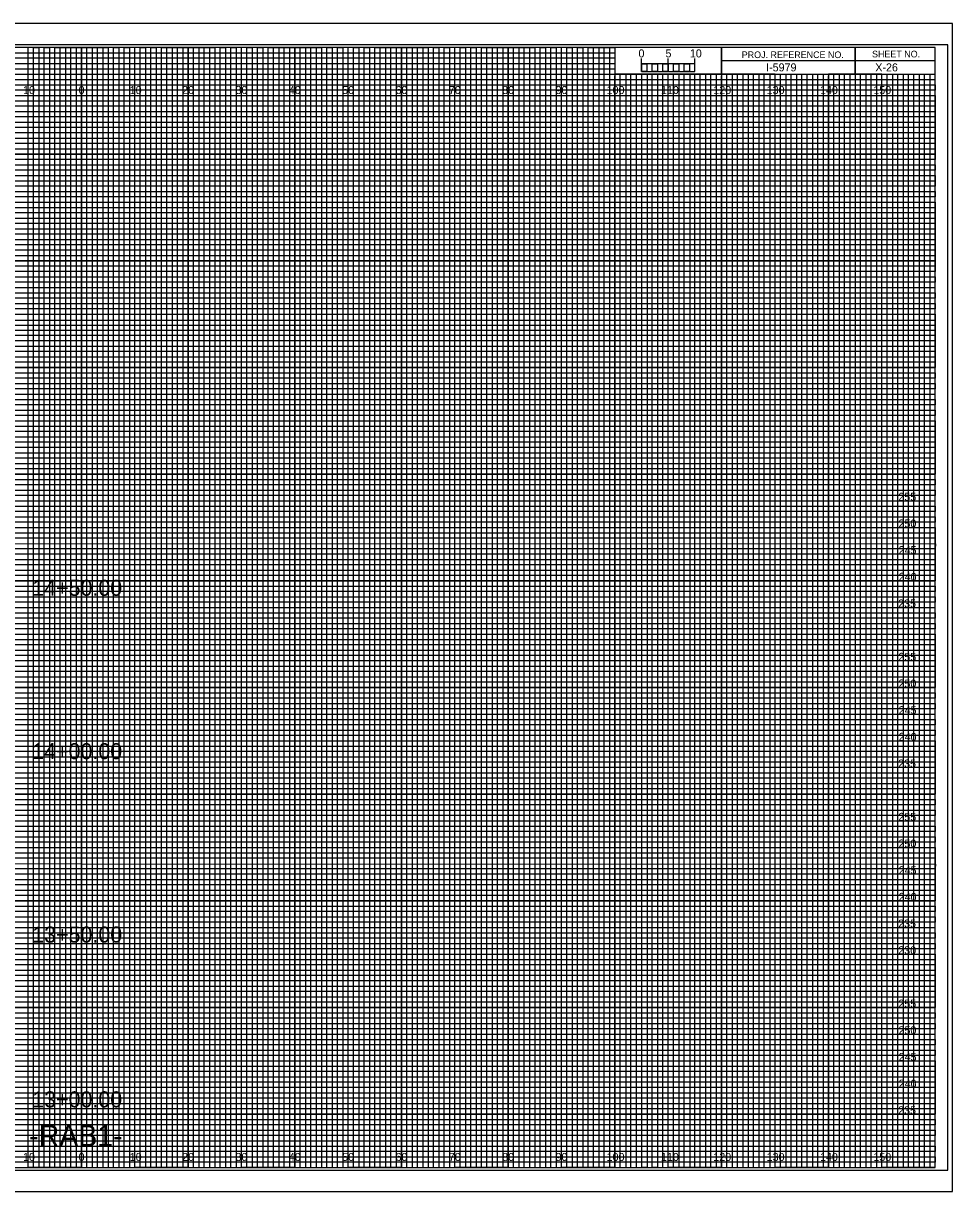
# Model space of a CAD drawing. Extents: x -13 to 323, y -5 to 434.
# Drawn here: x 149.1 to 323.3, y 215.5 to 434.5 of the extents above; entities that cross this region are included whole.
import ezdxf

# ---------------------------------------------------------------- set-up
doc = ezdxf.new("R2010")
doc.units = 0
for name, color, linetype in [('Exist CMT Pavement', 7, 'Continuous'), ('Exist Cross Section Cell', 7, 'Continuous'), ('Exist XS Center Line Elevation Label', 7, 'Continuous'), ('Exist XS Ground Line', 7, 'Continuous'), ('Prop CMT Conc Surface', 7, 'Continuous'), ('Prop CMT Concrete Structures', 7, 'Continuous'), ('Prop CMT DNC', 7, 'Continuous'), ('Prop CMT Pvmt Course 1 CG', 7, 'Continuous'), ('Prop CMT Pvmt Course 1 Wedge', 7, 'Continuous'), ('Prop CMT Pvmt Course 2', 7, 'Continuous'), ('Prop CMT Pvmt Course 2 Wedge', 7, 'Continuous'), ('Prop CMT Pvmt Course 3', 7, 'Continuous'), ('Prop CMT Pvmt Surface', 7, 'Continuous'), ('Prop CMT Pvmt Wedge Surface 1', 7, 'Continuous'), ('Prop CMT Shear Line', 7, 'Continuous'), ('Prop CMT Slope Grass', 7, 'Continuous'), ('Prop CMT Subgrade Earthwork', 7, 'Continuous')]:
    doc.layers.add(name, color=color, linetype=linetype)

msp = doc.modelspace()

# ---------------------------------------------------------------- linework, layer by layer
at = {"layer": 'Exist XS Center Line Elevation Label'}
for points in [[(145, 220), (155, 220), (155, 430), (165, 430), (165, 220), (175, 220), (175, 430), (185, 430), (185, 220), (195, 220), (195, 430), (205, 430), (205, 220), (215, 220), (215, 430), (225, 430), (225, 220), (235, 220), (235, 430), (245, 430), (245, 220), (255, 220), (255, 430), (259.93, 430), (260, 430), (260, 425), (264.99, 425), (264.99, 220), (275, 220), (275, 425), (285, 425), (285, 220), (295, 220), (295, 425), (305, 425), (305, 220), (315, 220), (315, 425)], [(0, 425), (275, 425)], [(0, 405), (320, 405), (320, 415), (0, 415)], [(0, 385), (320, 385), (320, 395), (0, 395)], [(0, 365), (320, 365), (320, 375), (0, 375)], [(0, 345), (320, 345), (320, 355), (0, 355)], [(0, 325), (320, 325), (320, 335), (0, 335)], [(0, 305), (320, 305), (320, 315), (0, 315)], [(0, 285), (320, 285), (320, 295), (0, 295)], [(0, 265), (320, 265), (320, 275), (0, 275)], [(0, 245), (320, 245), (320, 255), (0, 255)], [(0, 225), (320, 225), (320, 235), (0, 235)]]:
    msp.add_lwpolyline(points, dxfattribs=at)
at = {"layer": 'Exist XS Ground Line'}
for p, q in [((150, 430), (140, 430)), ((150, 220), (150, 430)), ((170, 430), (160, 430)), ((160, 430), (160, 220)), ((170, 220), (170, 430)), ((190, 430), (180, 430)), ((180, 430), (180, 220)), ((190, 220), (190, 430)), ((210, 430), (200, 430)), ((200, 430), (200, 220)), ((210, 220), (210, 430)), ((230, 430), (220, 430)), ((220, 430), (220, 220)), ((230, 220), (230, 430)), ((250, 430), (240, 430)), ((240, 430), (240, 220)), ((250, 220), (250, 430)), ((260, 430), (260, 220)), ((270, 220), (270, 425)), ((290, 425), (280, 425)), ((280, 425), (280, 220)), ((290, 220), (290, 425)), ((310, 425), (300, 425)), ((300, 425), (300, 220)), ((310, 220), (310, 425)), ((160, 220), (150, 220)), ((180, 220), (170, 220)), ((200, 220), (190, 220)), ((220, 220), (210, 220)), ((240, 220), (230, 220)), ((260, 220), (250, 220)), ((280, 220), (270, 220)), ((300, 220), (290, 220)), ((320, 220), (310, 220)), ((320, 220), (320, 220))]:
    msp.add_line(p, q, dxfattribs=at)
for points in [[(0, 420), (320, 420), (320, 410), (0, 410)], [(0, 400), (320, 400), (320, 390), (0, 390)], [(0, 380), (320, 380), (320, 370), (0, 370)], [(0, 360), (320, 360), (320, 350), (0, 350)], [(0, 340), (320, 340), (320, 330), (0, 330)], [(0, 320), (320, 320), (320, 310), (0, 310)], [(0, 300), (320, 300), (320, 290), (0, 290)], [(0, 280), (320, 280), (320, 270), (0, 270)], [(0, 260), (320, 260), (320, 250), (0, 250)], [(0, 240), (320, 240), (320, 230), (0, 230)]]:
    msp.add_lwpolyline(points, dxfattribs=at)
at = {"layer": 'Prop CMT Conc Surface'}
msp.add_lwpolyline([(-13.4, 215.5), (323.3, 215.5), (323.3, 434.5), (-13.4, 434.5)], close=True, dxfattribs=at)
at = {"layer": 'Prop CMT Concrete Structures'}
for p, q in [((305, 430), (305, 425)), ((305, 425), (305, 430)), ((280, 427.5), (280, 425)), ((320, 427.49), (280, 427.49)), ((280, 425), (320, 425))]:
    msp.add_line(p, q, dxfattribs=at)
for points in [[(320, 430), (0, 430), (0, 220), (320, 220)], [(280, 430), (260, 430), (260, 425.03), (280, 425.03)], [(320, 430), (280, 430), (280, 425), (320, 425)]]:
    msp.add_lwpolyline(points, close=True, dxfattribs=at)
at = {"layer": 'Prop CMT DNC'}
for p, q in [((267, 425), (266.01, 425)), ((266.01, 425), (266.01, 220)), ((267, 220), (267, 425)), ((269, 425), (268, 425)), ((268, 425), (268, 220)), ((269, 220), (269, 425)), ((266.01, 220), (265, 220)), ((268, 220), (267, 220))]:
    msp.add_line(p, q, dxfattribs=at)
for points in [[(150, 220), (151, 220), (151, 430), (152, 430), (152, 220)], [(152, 220), (153, 220), (153, 430), (154, 430), (154, 220)], [(155, 220), (156, 220), (156, 430), (157, 430), (157, 220)], [(157, 220), (158, 220), (158, 430), (159, 430), (159, 220)], [(160, 220), (161, 220), (161, 430), (162, 430), (162, 220)], [(162, 220), (163, 220), (163, 430), (164, 430), (164, 220)], [(165, 220), (166, 220), (166, 430), (167, 430), (167, 220)], [(167, 220), (168, 220), (168, 430), (169, 430), (169, 220)], [(170, 220), (171, 220), (171, 430), (172, 430), (172, 220)], [(172, 220), (173, 220), (173, 430), (174, 430), (174, 220)], [(175, 220), (176, 220), (176, 430), (177, 430), (177, 220)], [(177, 220), (178, 220), (178, 430), (179, 430), (179, 220)], [(180, 220), (181, 220), (181, 430), (182, 430), (182, 220)], [(182, 220), (183, 220), (183, 430), (184, 430), (184, 220)], [(185, 220), (186, 220), (186, 430), (187, 430), (187, 220)], [(187, 220), (188, 220), (188, 430), (189, 430), (189, 220)], [(190, 220), (191, 220), (191, 430), (192, 430), (192, 220)], [(192, 220), (193, 220), (193, 430), (194, 430), (194, 220)], [(195, 220), (196, 220), (196, 430), (197, 430), (197, 220)], [(197, 220), (198, 220), (198, 430), (199, 430), (199, 220)], [(200, 220), (201, 220), (201, 430), (202, 430), (202, 220)], [(202, 220), (203, 220), (203, 430), (204, 430), (204, 220)], [(205, 220), (206, 220), (206, 430), (207, 430), (207, 220)], [(207, 220), (208, 220), (208, 430), (209, 430), (209, 220)], [(210, 220), (211, 220), (211, 430), (212, 430), (212, 220)], [(212, 220), (213, 220), (213, 430), (214, 430), (214, 220)], [(215, 220), (216, 220), (216, 430), (217, 430), (217, 220)], [(217, 220), (218, 220), (218, 430), (219, 430), (219, 220)], [(220, 220), (221, 220), (221, 430), (222, 430), (222, 220)], [(222, 220), (223, 220), (223, 430), (224, 430), (224, 220)], [(225, 220), (226, 220), (226, 430), (227, 430), (227, 220)], [(227, 220), (228, 220), (228, 430), (229, 430), (229, 220)], [(230, 220), (231, 220), (231, 430), (232, 430), (232, 220)], [(232, 220), (233, 220), (233, 430), (234, 430), (234, 220)], [(235, 220), (236, 220), (236, 430), (237, 430), (237, 220)], [(237, 220), (238, 220), (238, 430), (239, 430), (239, 220)], [(240, 220), (241, 220), (241, 430), (242, 430), (242, 220)], [(242, 220), (243, 220), (243, 430), (244, 430), (244, 220)], [(245, 220), (246, 220), (246, 430), (247, 430), (247, 220)], [(247, 220), (248, 220), (248, 430), (249, 430), (249, 220)], [(250, 220), (251, 220), (251, 430), (252, 430), (252, 220)], [(252, 220), (253, 220), (253, 430), (254, 430), (254, 220)], [(255, 220), (256, 220), (256, 430), (257, 430), (257, 220)], [(257, 220), (258, 220), (258, 430), (259, 430), (259, 220)], [(260, 220), (261, 220), (261, 425), (262.02, 425), (262.02, 220)], [(262, 220), (263, 220), (263, 425), (263.99, 425), (263.99, 220)], [(270, 220), (270.98, 220), (270.98, 425), (272, 425), (272, 220)], [(272, 220), (273, 220), (273, 425), (274.05, 425), (274.05, 220)], [(275, 220), (276, 220), (276, 425), (277, 425), (277, 220)], [(277, 220), (278, 220), (278, 425), (279, 425), (279, 220)], [(280, 220), (281, 220), (281, 425), (282, 425), (282, 220)], [(282, 220), (283, 220), (283, 425), (284, 425), (284, 220)], [(285, 220), (286, 220), (286, 425), (287, 425), (287, 220)], [(287, 220), (288, 220), (288, 425), (289, 425), (289, 220)], [(290, 220), (291, 220), (291, 425), (292, 425), (292, 220)], [(292, 220), (293, 220), (293, 425), (294, 425), (294, 220)], [(295, 220), (296, 220), (296, 425), (297, 425), (297, 220)], [(297, 220), (298, 220), (298, 425), (299, 425), (299, 220)], [(300, 220), (301, 220), (301, 425), (302, 425), (302, 220)], [(302, 220), (303, 220), (303, 425), (304, 425), (304, 220)], [(305, 220), (306, 220), (306, 425), (307, 425), (307, 220)], [(307, 220), (308, 220), (308, 425), (309, 425), (309, 220)], [(310, 220), (311, 220), (311, 425), (312, 425), (312, 220)], [(312, 220), (313, 220), (313, 425), (314, 425), (314, 220)], [(315, 220), (316, 220), (316, 425), (317, 425), (317, 220)], [(317, 220), (318, 220), (318, 425), (319, 425), (319, 220)]]:
    msp.add_lwpolyline(points, dxfattribs=at)
at = {"layer": 'Prop CMT Pvmt Course 1 Wedge'}
for p, q in [((323.3, 434.5), (-13.4, 434.5)), ((-13.4, 215.5), (323.3, 215.5))]:
    msp.add_line(p, q, dxfattribs=at)
at = {"layer": 'Prop CMT Pvmt Course 2'}
msp.add_lwpolyline([(-10.8, 219.5), (322.4, 219.5), (322.4, 430.5), (-10.8, 430.5)], close=True, dxfattribs=at)
at = {"layer": 'Prop CMT Pvmt Course 3'}
for p, q in [((150, 220), (150, 430)), ((160, 220), (160, 430)), ((170, 220), (170, 430)), ((180, 220), (180, 430)), ((190, 220), (190, 430)), ((200, 220), (200, 430)), ((210, 220), (210, 430)), ((220, 220), (220, 430)), ((230, 220), (230, 430)), ((240, 220), (240, 430)), ((250, 220), (250, 430)), ((260, 220), (260, 424.69)), ((270, 220), (270, 424.69)), ((280, 220), (280, 424.69)), ((290, 220), (290, 424.69)), ((300, 220), (300, 424.69)), ((310, 220), (310, 424.69)), ((0, 420), (320, 420)), ((0, 410), (320, 410)), ((0, 400), (320, 400)), ((0, 390), (320, 390)), ((0, 380), (320, 380)), ((0, 370), (320, 370)), ((0, 360), (320, 360)), ((0, 350), (320, 350)), ((0, 340), (320, 340)), ((0, 330), (320, 330)), ((0, 320), (320, 320)), ((0, 310), (320, 310)), ((0, 300), (320, 300)), ((0, 290), (320, 290)), ((0, 280), (320, 280)), ((0, 270), (320, 270)), ((0, 260), (320, 260)), ((0, 250), (320, 250)), ((0, 240), (320, 240)), ((0, 230), (320, 230))]:
    msp.add_line(p, q, dxfattribs=at)
at = {"layer": 'Prop CMT Slope Grass'}
for p, q in [((265, 425.49), (265, 427.9)), ((265, 426.9), (265, 427.9)), ((270, 425.49), (270, 427.9)), ((275, 425.49), (275, 427.9)), ((275, 426.9), (275, 427.9))]:
    msp.add_line(p, q, dxfattribs=at)
for points in [[(275, 426.9), (265, 426.9), (265, 425.49), (275, 425.49)], [(265, 426.9), (266, 426.9), (266, 425.49), (265, 425.49)], [(267, 426.9), (268, 426.9), (268, 425.49), (267, 425.49)], [(269, 426.9), (270, 426.9), (270, 425.49), (269, 425.49)], [(271, 426.9), (272, 426.9), (272, 425.49), (271, 425.49)], [(273, 426.9), (274, 426.9), (274, 425.49), (273, 425.49)]]:
    msp.add_lwpolyline(points, close=True, dxfattribs=at)
at = {"layer": 'Prop CMT Subgrade Earthwork'}
for p, q in [((0, 429), (260, 429)), ((260, 427.98), (0, 427.98)), ((260, 429), (260, 427.98)), ((0, 427), (260, 427)), ((260, 425.89), (0, 425.89)), ((260, 427), (260, 425.89)), ((0, 424), (320, 424))]:
    msp.add_line(p, q, dxfattribs=at)
for points in [[(0, 423), (270, 423), (320, 423), (320, 422), (0, 422)], [(0, 421), (320, 421), (320, 419), (0, 419)], [(0, 418), (320, 418), (320, 417), (0, 416.98)], [(0, 416), (320, 416), (320, 414), (0, 414)], [(0, 413), (320, 413), (320, 412), (0, 412)], [(0, 411), (320, 411), (320, 409), (0, 409)], [(0, 408), (320, 408), (320, 407), (0, 407)], [(0, 406), (320, 406), (320, 404), (0, 404)], [(0, 403), (320, 403), (320, 402), (0, 402)], [(0, 401), (320, 401), (320, 399), (0, 399)], [(0, 398), (320, 398), (320, 397), (0, 397)], [(0, 396), (320, 396), (320, 393.95), (320, 393), (320, 392), (0, 392)], [(0, 394), (320, 394), (320, 393), (0, 393)], [(0, 391), (320, 391), (320, 389), (0, 389.03)], [(0, 389.03), (320, 389), (320, 388), (0, 388)], [(0, 387), (320, 387), (320, 386), (0, 386)], [(0, 384), (320, 384), (320, 383), (0, 383)], [(0, 382), (320, 382), (320, 381), (0, 381)], [(-0.07, 378.89), (320, 378.89), (320, 377.88), (-0.07, 377.88)], [(0, 377), (320, 377), (320, 376), (0, 376)], [(0, 374), (320, 374), (320, 373), (0, 373)], [(0, 372), (320, 372), (320, 371), (0, 371)], [(0, 369), (320, 369), (320, 368), (0, 368)], [(0, 367), (320, 367), (320, 366), (0, 366)], [(0, 364), (320, 364), (320, 363), (0, 363)], [(0, 362), (320, 362), (320, 361), (0, 361)], [(0, 359), (320, 359), (319.99, 357.98), (0, 358)], [(0, 357), (320, 357), (320, 356), (0, 356)], [(0, 354), (320, 354), (320, 353), (0, 353)], [(0, 352), (320, 352), (320, 351), (0, 351)], [(0, 349), (320, 349), (320, 348), (0, 348)], [(0, 347), (320, 347), (320, 346), (0, 346)], [(0, 344), (320, 344), (320, 343), (0, 343)], [(0, 342), (320, 342), (320, 341), (0, 341)], [(0, 339), (320, 339), (320, 338), (0, 338)], [(0, 336.99), (320.07, 336.91), (320, 336), (0, 336)], [(0, 334), (320, 334), (320, 333), (0, 333)], [(0, 332), (320, 332), (320, 331), (0, 331)], [(0, 329), (320, 329), (320, 328), (0, 328)], [(0, 327), (320, 327), (320, 326), (0, 326)], [(0, 324), (320, 324), (320, 323), (0, 323)], [(0, 322), (320, 322), (320, 321), (0, 321)], [(0, 319), (320, 319), (320, 318), (0, 318)], [(0, 317), (320, 317), (320, 316), (0, 316)], [(0, 314), (320, 314), (320, 313), (0, 313)], [(0, 312), (320, 312), (320, 311), (0, 311)], [(0, 309), (320, 309), (320, 308), (0, 308)], [(0, 307), (320, 307), (320, 306), (0, 306)], [(0, 304), (320, 304), (320, 303), (0, 303)], [(0, 302), (320, 302), (320, 301), (0, 301)], [(0, 299), (320, 299), (319.99, 297.98), (0, 298)], [(0, 297), (320, 297), (320, 296), (0, 296)], [(0, 294), (320, 294), (320, 293), (0, 293)], [(0, 292), (320, 292), (320, 291), (0, 291)], [(0, 289), (320, 289), (320, 288), (0, 288)], [(0, 287), (320, 287), (320, 286), (0, 286)], [(0, 284), (320, 284), (320, 283), (0, 283)], [(0, 282), (320, 282), (320, 281), (0, 281)], [(0, 279), (320, 279), (320, 278), (0, 278)], [(0, 276.99), (320.07, 276.91), (320, 276), (0, 276)], [(0, 274), (320, 274), (320, 273), (0, 273)], [(0, 272), (320, 272), (320, 271), (0, 271)], [(0, 269), (320, 269), (320, 268), (0, 268)], [(0, 267), (320, 267), (320, 266), (0, 266)], [(0, 264), (320, 264), (320, 263), (0, 263)], [(0, 262), (320, 262), (320, 261), (0, 261)], [(0, 259), (320, 259), (320, 258), (0, 258)], [(0, 257), (320, 257), (320, 256), (0, 256)], [(0, 254), (320, 254), (320, 253), (0, 253)], [(0, 252), (320, 252), (320, 251), (0, 251)], [(0, 249), (320, 249), (320, 248), (0, 248)], [(0, 247), (320, 247), (320, 246), (0, 246)], [(0, 244), (320, 244), (320, 243), (0, 243)], [(0, 242), (320, 242), (320, 241), (0, 241)], [(0, 239), (320, 239), (320, 238), (0, 238)], [(0, 237), (320, 237), (320, 236), (0, 236)], [(0, 234), (320, 234), (320, 233), (0, 233)], [(0, 232), (320, 232), (320, 231), (0, 231)], [(0, 229), (320, 229), (320, 228), (0, 228)], [(0, 227), (320, 227), (320, 226), (0, 226)], [(0, 224), (320, 224), (320, 223), (0, 223)], [(0, 222), (320, 222), (320, 221), (0, 221)]]:
    msp.add_lwpolyline(points, dxfattribs=at)

# ---------------------------------------------------------------- texts
at = {"layer": 'Exist CMT Pavement'}
msp.add_text('X-26', height=1.5, dxfattribs=at).set_placement((308.8, 425.5))
at = {"layer": 'Exist Cross Section Cell'}
for s, p in [('10', (149.04, 421.25)), ('0', (159.45, 421.25)), ('0', (159.45, 421.25)), ('10', (169.04, 421.25)), ('20', (178.86, 421.25)), ('30', (188.86, 421.25)), ('40', (198.86, 421.25)), ('50', (208.86, 421.25)), ('60', (218.86, 421.25)), ('70', (228.86, 421.25)), ('80', (238.86, 421.25)), ('90', (248.86, 421.25)), ('100', (258.44, 421.25)), ('110', (268.62, 421.25)), ('120', (278.44, 421.25)), ('130', (288.44, 421.25)), ('140', (298.44, 421.25)), ('150', (308.44, 421.25)), ('10', (149.04, 221.25)), ('0', (159.45, 221.25)), ('0', (159.45, 221.25)), ('10', (169.04, 221.25)), ('20', (178.86, 221.25)), ('30', (188.86, 221.25)), ('40', (198.86, 221.25)), ('50', (208.86, 221.25)), ('60', (218.86, 221.25)), ('70', (228.86, 221.25)), ('80', (238.86, 221.25)), ('90', (248.86, 221.25)), ('100', (258.44, 221.25)), ('110', (268.62, 221.25)), ('120', (278.44, 221.25)), ('130', (288.44, 221.25)), ('140', (298.44, 221.25)), ('150', (308.44, 221.25))]:
    msp.add_text(s, height=1.5, dxfattribs=at).set_placement(p)
at = {"layer": 'Prop CMT Concrete Structures'}
for s, p in [('PROJ. REFERENCE NO.', (283.77, 427.99)), ('SHEET NO.', (308.19, 428.12))]:
    msp.add_text(s, height=1.25, dxfattribs=at).set_placement(p)
at = {"layer": 'Prop CMT Pvmt Course 1 CG'}
msp.add_text('-RAB1-', height=4, dxfattribs=at).set_placement((150.18, 224))
at = {"layer": 'Prop CMT Pvmt Course 2 Wedge'}
for s, p in [('255', (313.13, 345)), ('250', (313.15, 340)), ('245', (313.18, 335)), ('240', (313.19, 330)), ('235', (313.09, 325)), ('255', (313.13, 315)), ('250', (313.15, 310)), ('245', (313.18, 305)), ('240', (313.19, 300)), ('235', (313.09, 295)), ('255', (313.13, 285)), ('250', (313.15, 280)), ('245', (313.18, 275)), ('240', (313.19, 270)), ('235', (313.09, 265)), ('230', (313.11, 260)), ('255', (313.13, 250)), ('250', (313.15, 245)), ('245', (313.18, 240)), ('240', (313.19, 235)), ('235', (313.09, 230))]:
    msp.add_text(s, height=1.5, dxfattribs=at).set_placement(p)
at = {"layer": 'Prop CMT Pvmt Surface'}
msp.add_text('I-5979', height=1.5, dxfattribs=at).set_placement((288.34, 425.5))
at = {"layer": 'Prop CMT Pvmt Wedge Surface 1'}
for s, p in [('5', (269.47, 428.12)), ('10', (274.04, 428.12))]:
    msp.add_text(s, height=1.5, dxfattribs=at).set_placement(p)
at = {"layer": 'Prop CMT Shear Line'}
for s, p in [('14+50.00', (150.77, 327.19)), ('14+00.00', (150.77, 296.57)), ('13+50.00', (150.77, 262.19)), ('13+00.00', (150.77, 231.3))]:
    msp.add_text(s, height=3, dxfattribs=at).set_placement(p)
at = {"layer": 'Prop CMT Slope Grass'}
msp.add_text('0', height=1.5, dxfattribs=at).set_placement((264.41, 428.12))

doc.saveas('drawing.dxf')
